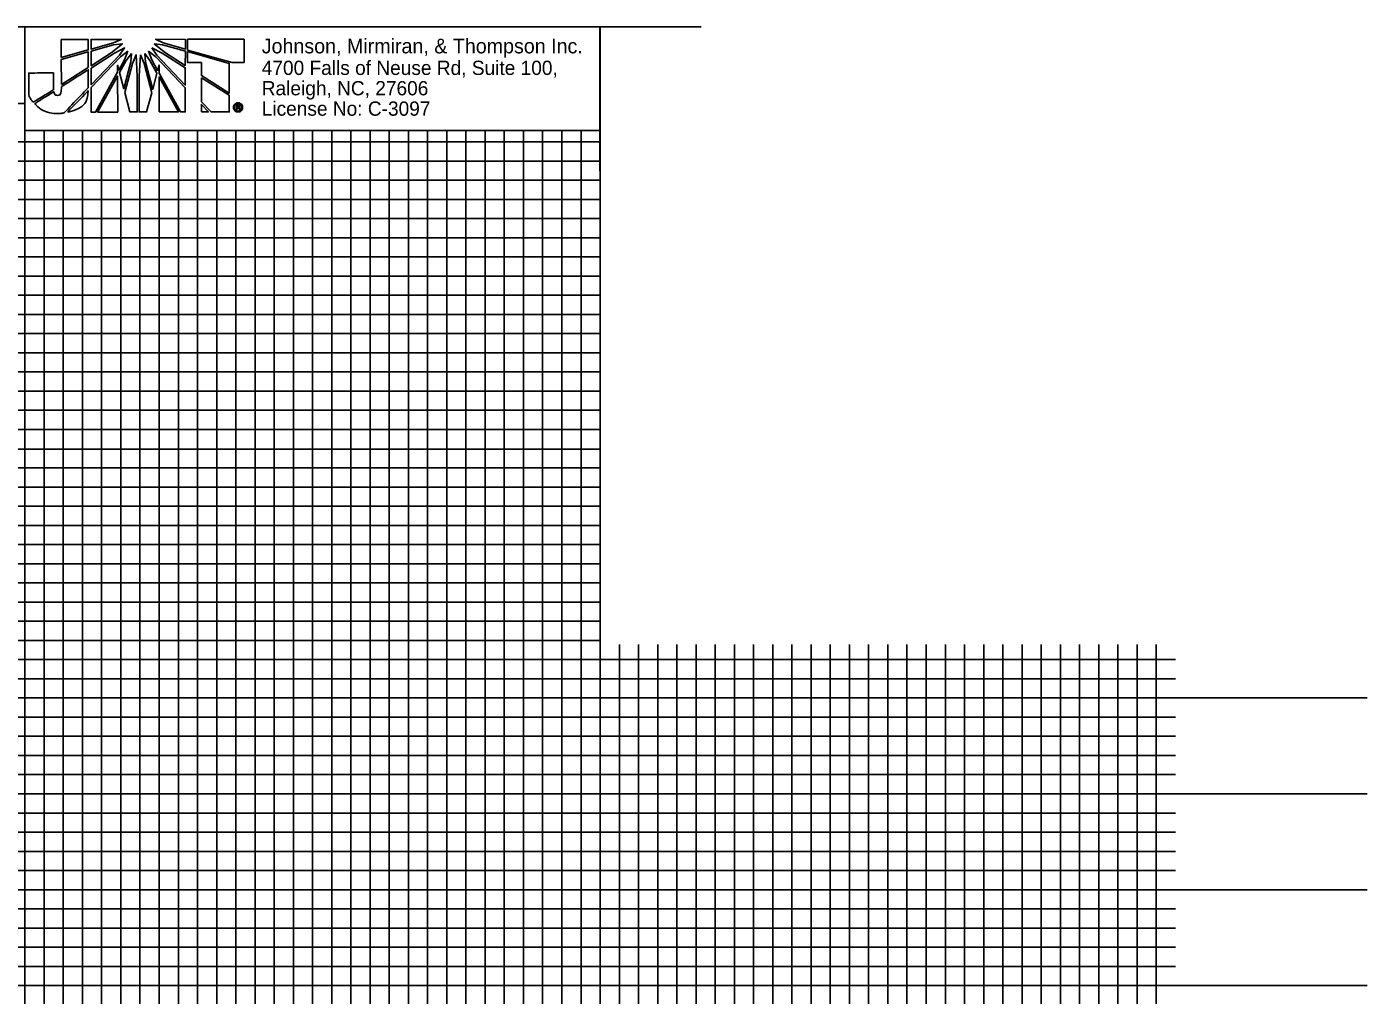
# Model space of a CAD drawing. Extents: x 1647943 to 1651624, y 802691 to 845761.
# Drawn here: x 1651274.9 to 1651624.4, y 845508.6 to 845761.1 of the extents above; entities that cross this region are included whole.
import ezdxf

# ---------------------------------------------------------------- set-up
doc = ezdxf.new("R2010")
doc.units = 0
for name, color, linetype in [('Prop Dimension Text', 7, 'Continuous'), ('Sheet Plan CELL', 7, 'Continuous'), ('Sheet Profile Grid Major CELL', 7, 'Continuous'), ('Sheet Profile Grid Middle CELL', 7, 'Continuous'), ('Sheet Profile Grid Minor CELL', 7, 'Continuous')]:
    doc.layers.add(name, color=color, linetype=linetype)

msp = doc.modelspace()

# ---------------------------------------------------------------- linework, layer by layer
at = {"layer": 'Prop Dimension Text'}
for p, q in [((1651290.93, 845757.76), (1651283.92, 845757.76)), ((1651283.92, 845757.76), (1651283.92, 845753.1)), ((1651290.94, 845755.05), (1651290.93, 845757.76)), ((1651299.56, 845757.81), (1651291.66, 845757.8)), ((1651291.66, 845757.8), (1651291.67, 845755.29)), ((1651291.67, 845755.29), (1651297.55, 845756.91)), ((1651296.94, 845754.28), (1651299.84, 845756.65)), ((1651297.55, 845756.91), (1651299.56, 845757.81)), ((1651299.84, 845756.65), (1651297.55, 845756.37)), ((1651308.11, 845756.66), (1651311.05, 845754.25)), ((1651310.27, 845756.38), (1651308.11, 845756.66)), ((1651316.28, 845757.79), (1651308.5, 845757.82)), ((1651308.5, 845757.82), (1651310.47, 845756.89)), ((1651316.28, 845754.73), (1651310.27, 845756.38)), ((1651310.47, 845756.89), (1651316.28, 845755.26)), ((1651316.28, 845755.26), (1651316.28, 845757.79)), ((1651331.58, 845757.84), (1651316.83, 845757.82)), ((1651316.83, 845757.82), (1651316.83, 845755.11)), ((1651331.58, 845751.79), (1651331.58, 845757.84)), ((1651283.92, 845753.1), (1651290.94, 845755.05)), ((1651290.94, 845754.54), (1651283.92, 845752.57)), ((1651290.94, 845750.48), (1651290.94, 845754.54)), ((1651297.55, 845756.37), (1651291.67, 845754.74)), ((1651291.67, 845754.74), (1651291.67, 845750.94)), ((1651291.67, 845750.94), (1651296.94, 845754.28)), ((1651297.75, 845754.2), (1651291.67, 845750.33)), ((1651291.67, 845745.95), (1651299.07, 845753.66)), ((1651299.37, 845753.28), (1651291.67, 845745.21)), ((1651300.42, 845755.56), (1651297.75, 845754.2)), ((1651299.07, 845753.66), (1651300.42, 845755.56)), ((1651301.23, 845754.72), (1651299.37, 845753.28)), ((1651300.38, 845752.47), (1651301.23, 845754.72)), ((1651302.24, 845754.09), (1651300.85, 845752.31)), ((1651302.04, 845751.93), (1651302.24, 845754.09)), ((1651303.4, 845753.78), (1651302.44, 845751.53)), ((1651303.7, 845748.25), (1651303.4, 845753.78)), ((1651304.56, 845753.78), (1651304.2, 845748.25)), ((1651305.48, 845751.54), (1651304.56, 845753.78)), ((1651305.68, 845754.1), (1651305.91, 845751.85)), ((1651307.03, 845752.31), (1651305.68, 845754.1)), ((1651306.67, 845754.72), (1651307.53, 845752.48)), ((1651308.54, 845753.29), (1651306.67, 845754.72)), ((1651307.49, 845755.57), (1651308.85, 845753.64)), ((1651310.21, 845754.22), (1651307.49, 845755.57)), ((1651316.25, 845745.17), (1651308.54, 845753.29)), ((1651308.85, 845753.64), (1651316.25, 845745.9)), ((1651316.24, 845750.39), (1651310.21, 845754.22)), ((1651311.05, 845754.25), (1651316.24, 845751.01)), ((1651316.24, 845751.01), (1651316.28, 845754.73)), ((1651316.83, 845755.11), (1651316.83, 845755.03)), ((1651316.83, 845755.03), (1651328.45, 845751.79)), ((1651316.83, 845754.62), (1651316.83, 845754.57)), ((1651327.71, 845751.52), (1651316.83, 845754.62)), ((1651316.83, 845754.57), (1651316.83, 845751.74)), ((1651283.92, 845752.57), (1651283.93, 845746.03)), ((1651283.93, 845746.03), (1651290.94, 845750.48)), ((1651291.67, 845750.33), (1651291.67, 845745.95)), ((1651298.56, 845749.21), (1651298.56, 845751.07)), ((1651298.56, 845751.07), (1651298.91, 845749.79)), ((1651298.91, 845749.79), (1651300.38, 845752.47)), ((1651300.85, 845752.31), (1651299.11, 845749.13)), ((1651300.23, 845744.92), (1651302.04, 845751.93)), ((1651302.44, 845751.53), (1651300.47, 845743.95)), ((1651307.51, 845743.84), (1651305.48, 845751.54)), ((1651305.91, 845751.85), (1651307.74, 845744.76)), ((1651308.86, 845749.03), (1651307.03, 845752.31)), ((1651307.53, 845752.48), (1651309.04, 845749.69)), ((1651309.04, 845749.69), (1651309.4, 845751.08)), ((1651309.4, 845751.08), (1651309.4, 845749.03)), ((1651316.25, 845745.9), (1651316.24, 845750.39)), ((1651316.83, 845751.74), (1651320.43, 845751.75)), ((1651320.43, 845751.75), (1651320.44, 845748.38)), ((1651327.71, 845743.78), (1651327.71, 845751.52)), ((1651328.45, 845751.79), (1651331.58, 845751.79)), ((1651292.84, 845738.84), (1651298.56, 845749.21)), ((1651298.56, 845748.21), (1651293.38, 845738.84)), ((1651298.62, 845738.85), (1651298.56, 845748.21)), ((1651299.11, 845749.13), (1651300.23, 845744.92)), ((1651303.71, 845738.89), (1651303.7, 845748.25)), ((1651304.2, 845748.25), (1651304.21, 845738.89)), ((1651307.74, 845744.76), (1651308.86, 845749.03)), ((1651309.4, 845749.03), (1651315.01, 845738.87)), ((1651314.44, 845738.9), (1651309.4, 845748.02)), ((1651309.4, 845748.02), (1651309.41, 845738.89)), ((1651320.44, 845748.38), (1651327.71, 845743.78)), ((1651320.44, 845747.8), (1651320.44, 845741.52)), ((1651327.71, 845743.23), (1651320.44, 845747.8)), ((1651291.67, 845745.21), (1651291.68, 845738.84)), ((1651300.47, 845743.95), (1651301.79, 845738.89)), ((1651306.16, 845738.89), (1651307.51, 845743.84)), ((1651316.25, 845738.87), (1651316.25, 845745.17)), ((1651327.72, 845738.88), (1651327.71, 845743.23)), ((1651320.44, 845741.52), (1651322.96, 845738.87)), ((1651322.26, 845738.87), (1651320.44, 845740.84)), ((1651320.44, 845740.84), (1651320.45, 845738.87)), ((1651329.56, 845739.54), (1651329.56, 845740.61)), ((1651329.56, 845740.61), (1651330, 845740.61)), ((1651329.81, 845739.54), (1651329.56, 845739.54)), ((1651330, 845740.41), (1651329.81, 845740.41)), ((1651329.81, 845740.41), (1651329.81, 845740.16)), ((1651329.81, 845740.16), (1651330, 845740.16)), ((1651330, 845739.96), (1651329.81, 845739.96)), ((1651329.81, 845739.96), (1651329.81, 845739.54)), ((1651330, 845741.25), (1651330, 845741.02)), ((1651330, 845741.02), (1651330, 845741.25)), ((1651330, 845740.61), (1651330, 845740.41)), ((1651330, 845740.41), (1651330, 845740.61)), ((1651330, 845740.61), (1651330.07, 845740.61)), ((1651330.03, 845740.41), (1651330, 845740.41)), ((1651330, 845740.16), (1651330, 845739.96)), ((1651330, 845739.96), (1651330, 845740.16)), ((1651330, 845740.16), (1651330.01, 845740.16)), ((1651330.01, 845739.96), (1651330, 845739.96)), ((1651330, 845739.12), (1651330, 845738.89)), ((1651330, 845738.89), (1651330, 845739.12)), ((1651330, 845739.12), (1651330.01, 845739.12)), ((1651291.68, 845738.84), (1651292.84, 845738.84)), ((1651293.38, 845738.84), (1651298.62, 845738.85)), ((1651301.79, 845738.89), (1651303.71, 845738.89)), ((1651304.21, 845738.89), (1651306.16, 845738.89)), ((1651309.41, 845738.89), (1651314.44, 845738.9)), ((1651315.01, 845738.87), (1651316.25, 845738.87)), ((1651320.45, 845738.87), (1651322.26, 845738.87)), ((1651322.96, 845738.87), (1651327.72, 845738.88)), ((1651330.01, 845738.89), (1651330, 845738.89))]:
    msp.add_line(p, q, dxfattribs=at)
msp.add_lwpolyline([(1651274.43, 845734.02), (1651424.38, 845734.02), (1651424.38, 845761.08), (1651274.43, 845761.08)], close=True, dxfattribs=at)
for points in [[(1651283.92, 845753.1), (1651290.94, 845755.05), (1651290.93, 845757.76), (1651283.92, 845757.76), (1651283.92, 845753.1)], [(1651297.55, 845756.91), (1651299.56, 845757.81), (1651291.66, 845757.8), (1651291.67, 845755.29), (1651297.55, 845756.91)], [(1651291.67, 845754.74), (1651291.67, 845750.94), (1651296.94, 845754.28), (1651299.84, 845756.65), (1651297.55, 845756.37), (1651291.67, 845754.74)], [(1651308.11, 845756.66), (1651311.05, 845754.25), (1651316.24, 845751.01), (1651316.28, 845754.73), (1651310.27, 845756.38), (1651308.11, 845756.66)], [(1651310.47, 845756.89), (1651316.28, 845755.26), (1651316.28, 845757.79), (1651308.5, 845757.82), (1651310.47, 845756.89)], [(1651331.58, 845757.84), (1651316.83, 845757.82), (1651316.83, 845755.11), (1651316.83, 845755.03), (1651328.45, 845751.79), (1651331.58, 845751.79), (1651331.58, 845757.84)], [(1651283.93, 845746.03), (1651290.94, 845750.48), (1651290.94, 845754.54), (1651283.92, 845752.57), (1651283.93, 845746.03)], [(1651291.67, 845750.33), (1651291.67, 845745.95), (1651299.07, 845753.66), (1651300.42, 845755.56), (1651297.75, 845754.2), (1651291.67, 845750.33)], [(1651301.23, 845754.72), (1651299.37, 845753.28), (1651291.67, 845745.21), (1651291.68, 845738.84), (1651292.84, 845738.84), (1651298.56, 845749.21), (1651298.56, 845751.07), (1651298.91, 845749.79), (1651300.38, 845752.47), (1651301.23, 845754.72)], [(1651302.24, 845754.09), (1651300.85, 845752.31), (1651299.11, 845749.13), (1651300.23, 845744.92), (1651302.04, 845751.93), (1651302.24, 845754.09)], [(1651302.44, 845751.53), (1651300.47, 845743.95), (1651301.79, 845738.89), (1651303.71, 845738.89), (1651303.7, 845748.25), (1651303.4, 845753.78), (1651302.44, 845751.53)], [(1651304.56, 845753.78), (1651304.2, 845748.25), (1651304.21, 845738.89), (1651306.16, 845738.89), (1651307.51, 845743.84), (1651305.48, 845751.54), (1651304.56, 845753.78)], [(1651305.68, 845754.1), (1651305.91, 845751.85), (1651307.74, 845744.76), (1651308.86, 845749.03), (1651307.03, 845752.31), (1651305.68, 845754.1)], [(1651306.67, 845754.72), (1651307.53, 845752.48), (1651309.04, 845749.69), (1651309.4, 845751.08), (1651309.4, 845749.03), (1651315.01, 845738.87), (1651316.25, 845738.87), (1651316.25, 845745.17), (1651308.54, 845753.29), (1651306.67, 845754.72)], [(1651307.49, 845755.57), (1651308.85, 845753.64), (1651316.25, 845745.9), (1651316.24, 845750.39), (1651310.21, 845754.22), (1651307.49, 845755.57)], [(1651316.83, 845754.62), (1651316.83, 845754.57), (1651316.83, 845751.74), (1651320.43, 845751.75), (1651320.44, 845748.38), (1651327.71, 845743.78), (1651327.71, 845751.52), (1651316.83, 845754.62)], [(1651293.38, 845738.84), (1651298.62, 845738.85), (1651298.56, 845748.21), (1651293.38, 845738.84)], [(1651309.41, 845738.89), (1651314.44, 845738.9), (1651309.4, 845748.02), (1651309.41, 845738.89)], [(1651320.44, 845747.8), (1651320.44, 845741.52), (1651322.96, 845738.87), (1651327.72, 845738.88), (1651327.71, 845743.23), (1651320.44, 845747.8), (1651320.44, 845747.8)], [(1651320.45, 845738.87), (1651320.45, 845738.87), (1651322.26, 845738.87), (1651320.44, 845740.84), (1651320.45, 845738.87)], [(1651330.47, 845739.8), (1651330.47, 845739.74), (1651330.48, 845739.7), (1651330.48, 845739.66), (1651330.51, 845739.54), (1651330.29, 845739.54)]]:
    msp.add_lwpolyline(points, dxfattribs=at)
for points, degree in [([(1651282.92, 845743.19), (1651282.51, 845743.19), (1651282.15, 845743.42), (1651282, 845744.2), (1651282, 845744.2), (1651276.96, 845741.08), (1651276.96, 845741.08), (1651278.51, 845739.44), (1651280.99, 845738.47), (1651283.09, 845738.48), (1651283.63, 845738.48), (1651284.05, 845738.52), (1651284.63, 845738.64), (1651284.63, 845738.64), (1651290.95, 845745.18), (1651290.95, 845745.18), (1651290.95, 845745.18), (1651290.94, 845749.9), (1651290.94, 845749.9), (1651290.94, 845749.9), (1651283.93, 845745.44), (1651283.93, 845745.44), (1651283.93, 845743.66), (1651283.5, 845743.19), (1651282.92, 845743.19)], 3), ([(1651282.92, 845743.19), (1651282.51, 845743.19), (1651282.15, 845743.42), (1651282, 845744.2), (1651282, 845744.2), (1651276.96, 845741.08), (1651276.96, 845741.08), (1651278.51, 845739.44), (1651280.99, 845738.47), (1651283.09, 845738.48), (1651283.63, 845738.48), (1651284.05, 845738.52), (1651284.63, 845738.64), (1651284.63, 845738.64), (1651290.95, 845745.18), (1651290.95, 845745.18), (1651290.95, 845745.18), (1651290.94, 845749.9), (1651290.94, 845749.9), (1651290.94, 845749.9), (1651283.93, 845745.44), (1651283.93, 845745.44), (1651283.93, 845743.66), (1651283.5, 845743.19), (1651282.92, 845743.19)], 3), ([(1651281.91, 845749.04), (1651281.91, 845749.04), (1651275.41, 845749.03), (1651275.41, 845749.03), (1651275.41, 845749.03), (1651275.42, 845744.96), (1651275.42, 845744.96), (1651275.42, 845744.96), (1651275.42, 845744.54), (1651275.42, 845744.54), (1651275.42, 845743.26), (1651275.84, 845742.26), (1651276.58, 845741.41), (1651276.58, 845741.41), (1651281.91, 845744.66), (1651281.91, 845744.74), (1651281.91, 845744.74), (1651281.91, 845749.04), (1651281.91, 845749.04)], 3), ([(1651290.95, 845744.44), (1651290.95, 845744.44), (1651285.49, 845738.79), (1651285.49, 845738.79), (1651288.16, 845739.45), (1651290.82, 845741.23), (1651290.95, 845744.44)], 3), ([(1651330, 845738.89), (1651329.68, 845738.89), (1651329.4, 845739), (1651329.17, 845739.24), (1651328.93, 845739.46), (1651328.81, 845739.75), (1651328.81, 845740.08), (1651328.81, 845740.41), (1651328.93, 845740.69), (1651329.16, 845740.91), (1651329.4, 845741.13), (1651329.67, 845741.25), (1651330, 845741.25)], 3), ([(1651330, 845741.02), (1651329.74, 845741.02), (1651329.51, 845740.94), (1651329.33, 845740.76), (1651329.14, 845740.57), (1651329.05, 845740.34), (1651329.05, 845740.08), (1651329.05, 845739.81), (1651329.15, 845739.58), (1651329.33, 845739.4), (1651329.52, 845739.21), (1651329.74, 845739.12), (1651330, 845739.12)], 3), ([(1651330, 845741.25), (1651330.33, 845741.25), (1651330.62, 845741.13), (1651330.85, 845740.91), (1651331.09, 845740.69), (1651331.2, 845740.41), (1651331.2, 845740.08)], 3), ([(1651330.01, 845739.12), (1651330.28, 845739.12), (1651330.5, 845739.21), (1651330.69, 845739.4), (1651330.87, 845739.58), (1651330.97, 845739.82), (1651330.97, 845740.08), (1651330.97, 845740.34), (1651330.87, 845740.58), (1651330.69, 845740.76), (1651330.5, 845740.94), (1651330.28, 845741.02), (1651330, 845741.02)], 3), ([(1651330.01, 845740.16), (1651330.17, 845740.16), (1651330.25, 845740.21), (1651330.25, 845740.29), (1651330.25, 845740.37), (1651330.18, 845740.41), (1651330.03, 845740.41)], 3), ([(1651331.2, 845740.08), (1651331.2, 845739.75), (1651331.09, 845739.47), (1651330.86, 845739.23), (1651330.63, 845739.01), (1651330.35, 845738.89), (1651330.01, 845738.89)], 3), ([(1651330.2, 845739.92), (1651330.17, 845739.94), (1651330.11, 845739.96), (1651330.01, 845739.96)], 2), ([(1651330.07, 845740.61), (1651330.34, 845740.62), (1651330.48, 845740.51), (1651330.48, 845740.29), (1651330.48, 845740.2), (1651330.44, 845740.12), (1651330.35, 845740.06)], 3), ([(1651330.29, 845739.54), (1651330.26, 845739.6), (1651330.24, 845739.66), (1651330.24, 845739.74), (1651330.24, 845739.83), (1651330.23, 845739.89), (1651330.2, 845739.92)], 3), ([(1651330.35, 845740.06), (1651330.42, 845740.02), (1651330.46, 845739.93), (1651330.47, 845739.8)], 2)]:
    msp.add_open_spline(points, degree=degree, dxfattribs=at)
at = {"layer": 'Sheet Plan CELL'}
msp.add_line((1651424.38, 845735.99), (1651424.38, 845723.5), dxfattribs=at)
msp.add_line((1651424.38, 845735.99), (1651424.38, 845723.5), dxfattribs=at)
at = {"layer": 'Sheet Profile Grid Major CELL'}
for points in [[(1650824.43, 845761.08), (1650874.43, 845761.08), (1650874.43, 845261.08), (1650924.43, 845261.08), (1650924.43, 845761.08), (1650974.43, 845761.08), (1650974.43, 845261.08), (1651024.43, 845261.08), (1651024.43, 845761.08), (1651074.43, 845761.08), (1651074.43, 845261.08), (1651124.43, 845261.08), (1651124.43, 845761.08), (1651174.43, 845761.08), (1651174.43, 845261.08), (1651224.43, 845261.08), (1651224.43, 845761.08), (1651274.43, 845761.08), (1651274.43, 845261.08), (1651324.43, 845261.08), (1651324.43, 845734.02)], [(1651324.43, 845761.08), (1651374.43, 845761.08)], [(1651374.43, 845734.02), (1651374.43, 845261.08), (1651424.43, 845261.08), (1651424.43, 845761.08), (1651450.73, 845761.08)], [(1650124.43, 845711.08), (1651424.43, 845711.08)], [(1651424.43, 845661.08), (1650124.43, 845661.08), (1650124.43, 845611.08), (1651424.43, 845611.08)], [(1651474.43, 845600.03), (1651474.43, 845261.08), (1651524.43, 845261.08), (1651524.43, 845261.08), (1651524.43, 845600.03)], [(1651624.43, 845561.08), (1650124.43, 845561.08), (1650124.43, 845511.08), (1651624.43, 845511.08)]]:
    msp.add_lwpolyline(points, dxfattribs=at)
at = {"layer": 'Sheet Profile Grid Middle CELL'}
for points in [[(1650849.43, 845761.08), (1650899.43, 845761.08), (1650899.43, 845261.08), (1650949.43, 845261.08), (1650949.43, 845761.08), (1650999.43, 845761.08), (1650999.43, 845261.08), (1651049.43, 845261.08), (1651049.43, 845761.08), (1651099.43, 845761.08), (1651099.43, 845261.08), (1651149.43, 845261.08), (1651149.43, 845761.08), (1651199.43, 845761.08), (1651199.43, 845261.08), (1651249.43, 845261.08), (1651249.43, 845761.08), (1651299.43, 845761.08)], [(1651349.43, 845761.08), (1651399.43, 845761.08)], [(1651299.43, 845734.02), (1651299.43, 845261.08), (1651349.43, 845261.08), (1651349.43, 845734.02)], [(1651399.43, 845734.02), (1651399.43, 845261.08), (1651449.43, 845261.08), (1651449.43, 845600.03)], [(1651424.43, 845686.08), (1650124.43, 845686.08), (1650124.43, 845636.08), (1651424.43, 845636.08)], [(1651449.43, 845523.88), (1651449.43, 845261.08), (1651499.43, 845261.08), (1651499.43, 845600.03)], [(1651499.43, 845523.88), (1651499.43, 845261.08), (1651549.43, 845261.08), (1651549.43, 845600.03)], [(1651624.43, 845586.08), (1650124.43, 845586.08), (1650124.43, 845536.08), (1651449.43, 845536.08)], [(1651449.43, 845536.08), (1651624.43, 845536.08)], [(1651449.43, 845536.08), (1651624.43, 845536.08)]]:
    msp.add_lwpolyline(points, dxfattribs=at)
at = {"layer": 'Sheet Profile Grid Minor CELL'}
for p, q in [((1651424.38, 845756.08), (1651424.43, 845756.08)), ((1651424.43, 845751.08), (1651424.38, 845751.08)), ((1651424.38, 845746.08), (1651424.43, 845746.08)), ((1651424.38, 845626.08), (1650174.43, 845626.08)), ((1651424.43, 845621.08), (1650174.43, 845621.08)), ((1651424.43, 845616.08), (1650174.43, 845616.08)), ((1650174.43, 845606.08), (1651424.43, 845606.08)), ((1651424.43, 845601.08), (1650174.43, 845601.08)), ((1650174.43, 845596.08), (1651574.43, 845596.08)), ((1651574.43, 845576.08), (1650174.43, 845576.08)), ((1650174.43, 845571.08), (1651574.43, 845571.08)), ((1651574.43, 845551.08), (1650174.43, 845551.08)), ((1650174.43, 845546.08), (1651574.43, 845546.08)), ((1651574.43, 845526.08), (1650174.43, 845526.08)), ((1650174.43, 845521.08), (1651574.43, 845521.08)), ((1651574.43, 845516.08), (1650174.43, 845516.08))]:
    msp.add_line(p, q, dxfattribs=at)
for points in [[(1651269.43, 845761.08), (1651279.43, 845761.08)], [(1651284.43, 845761.08), (1651289.43, 845761.08)], [(1651294.43, 845761.08), (1651304.43, 845761.08)], [(1651309.43, 845761.08), (1651314.43, 845761.08)], [(1651319.43, 845761.08), (1651329.43, 845761.08)], [(1651334.43, 845761.08), (1651339.43, 845761.08)], [(1651344.43, 845761.08), (1651354.43, 845761.08)], [(1651359.43, 845761.08), (1651364.43, 845761.08)], [(1651369.43, 845761.08), (1651379.43, 845761.08)], [(1651384.43, 845761.08), (1651389.43, 845761.08)], [(1651394.43, 845761.08), (1651404.43, 845761.08)], [(1651409.43, 845761.08), (1651414.43, 845761.08)], [(1651419.43, 845761.08), (1651429.43, 845761.08)], [(1651274.43, 845741.08), (1650174.43, 845741.08), (1650174.43, 845731.08), (1651424.43, 845731.08)], [(1651424.43, 845741.08), (1651424.38, 845741.08)], [(1651279.43, 845734.02), (1651279.43, 845261.08), (1651284.43, 845261.08), (1651284.43, 845734.02)], [(1651289.43, 845734.02), (1651289.43, 845261.08), (1651294.43, 845261.08), (1651294.43, 845734.02)], [(1651304.43, 845734.02), (1651304.43, 845261.08), (1651309.43, 845261.08), (1651309.43, 845734.02)], [(1651314.43, 845261.08), (1651319.43, 845261.08), (1651319.43, 845734.02)], [(1651314.43, 845734.02), (1651314.43, 845261.08)], [(1651329.43, 845734.02), (1651329.43, 845261.08), (1651334.43, 845261.08), (1651334.43, 845734.02)], [(1651339.43, 845734.02), (1651339.43, 845261.08), (1651344.43, 845261.08), (1651344.43, 845734.02)], [(1651354.43, 845734.02), (1651354.43, 845261.08), (1651359.43, 845261.08), (1651359.43, 845734.02)], [(1651364.43, 845734.02), (1651364.43, 845261.08), (1651369.43, 845261.08), (1651369.43, 845734.02)], [(1651379.43, 845734.02), (1651379.43, 845261.08), (1651384.43, 845261.08), (1651384.43, 845734.02)], [(1651389.43, 845734.02), (1651389.43, 845261.08), (1651394.43, 845261.08), (1651394.43, 845734.02)], [(1651404.43, 845734.02), (1651404.43, 845261.08), (1651409.43, 845261.08), (1651409.43, 845734.02)], [(1651414.43, 845734.02), (1651414.43, 845261.08), (1651419.43, 845261.08), (1651419.43, 845734.02)], [(1651424.38, 845726.08), (1650174.43, 845726.08), (1650174.43, 845721.08), (1651424.43, 845721.08)], [(1651424.43, 845716.08), (1650174.43, 845716.08), (1650174.43, 845706.08), (1651424.43, 845706.08)], [(1651424.43, 845701.08), (1650174.43, 845701.08), (1650174.43, 845696.08), (1651424.43, 845696.08)], [(1651424.43, 845691.08), (1650174.43, 845691.08), (1650174.43, 845681.08), (1651424.43, 845681.08)], [(1651424.43, 845676.08), (1650174.43, 845676.08), (1650174.43, 845671.08), (1651424.43, 845671.08)], [(1651424.43, 845666.08), (1650174.43, 845666.08), (1650174.43, 845656.08), (1651424.43, 845656.08)], [(1651424.43, 845650.98), (1650174.53, 845650.98), (1650174.53, 845646.08), (1651424.43, 845646.08)], [(1651424.43, 845641.08), (1650174.43, 845641.08), (1650174.43, 845631.08), (1651424.43, 845631.08)], [(1651429.43, 845600.03), (1651429.43, 845261.08), (1651434.43, 845261.08), (1651434.43, 845600.03)], [(1651439.43, 845600.03), (1651439.43, 845261.08), (1651444.43, 845261.08), (1651444.43, 845600.03)], [(1651454.43, 845600.03), (1651454.43, 845261.08), (1651454.43, 845261.08), (1651459.43, 845261.08), (1651464.43, 845261.08), (1651464.43, 845600.03)], [(1651459.43, 845600.03), (1651459.43, 845261.08)], [(1651469.42, 845600.03), (1651469.33, 845261.13), (1651474.33, 845261.13), (1651479.43, 845261.08), (1651479.43, 845600.03)], [(1651479.43, 845523.88), (1651479.43, 845261.08), (1651484.43, 845261.08), (1651484.43, 845600.03)], [(1651489.43, 845600.03), (1651489.43, 845261.08), (1651494.43, 845261.08), (1651494.43, 845600.03)], [(1651504.43, 845600.03), (1651504.43, 845261.08), (1651509.43, 845261.08), (1651509.43, 845600.03)], [(1651514.43, 845600.03), (1651514.43, 845261.08), (1651519.43, 845261.08), (1651519.43, 845600.03)], [(1651529.43, 845600.03), (1651529.43, 845261.08), (1651534.43, 845261.08), (1651534.43, 845600.03)], [(1651539.43, 845600.03), (1651539.43, 845261.08), (1651544.43, 845261.08), (1651544.43, 845600.03)], [(1651554.43, 845600.03), (1651554.43, 845261.08), (1651559.43, 845261.08), (1651559.43, 845600.03)], [(1651564.43, 845600.03), (1651564.43, 845261.08), (1651569.43, 845261.08), (1651569.43, 845600.03)], [(1651574.43, 845591.08), (1650174.43, 845591.08), (1650174.43, 845581.08), (1651574.43, 845581.08)], [(1651574.43, 845566.08), (1650174.43, 845566.08), (1650174.43, 845556.08), (1651574.43, 845556.08)], [(1651574.43, 845541.08), (1650174.43, 845541.08), (1650174.43, 845531.08), (1651574.43, 845531.08)]]:
    msp.add_lwpolyline(points, dxfattribs=at)

# ---------------------------------------------------------------- texts
at = {"layer": 'Prop Dimension Text'}
for s, height, p in [('Johnson, Mirmiran, & Thompson Inc.', 3.8315, (1651336.18, 845754.15)), ('4700 Falls of Neuse Rd, Suite 100, ', 3.722, (1651336.18, 845748.52)), ('Raleigh, NC, 27606', 3.722, (1651336.18, 845743.21)), ('License No: C-3097', 3.722, (1651336.18, 845737.89))]:
    msp.add_text(s, height=height, rotation=360, dxfattribs=at).set_placement(p)

doc.saveas('drawing.dxf')
